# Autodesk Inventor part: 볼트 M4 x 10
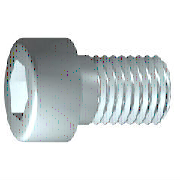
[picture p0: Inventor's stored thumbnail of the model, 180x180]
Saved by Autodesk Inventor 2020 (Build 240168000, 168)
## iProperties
IsCustomPart: 1
Created: 2012-02
Part Number: 볼트 M4 x 10
Material: 스테인리스강
Description: 6각 소켓 머리 캡 나사
Document SubType Name: Modeling
Standard: ISO 4762
Designer: mduedu
Standard Revision: Fourth edition 2004-03-01
Standards Organization: ISO
Language: ko-KR
Size Designation: M4 x 8
Categories: <MemberInstance><Categories><Category DisplayName="조임쇠" InternalName="e4da775c-781d-43d5-af7c-5136215cf5a6" Mnemonic="FSTN"><Category DisplayName="볼트" InternalN
Density: 7.75 g/cm^3
Appearance: 반광택
Author: mduedu
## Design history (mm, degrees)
sketch "스케치1"
  geometry: L1 (-1, 0)-(10, 0); L2 (10, 0)-(10, 2); L3 (10, 2)-(2.1, 2); L4 (2.1, 2)-(1.67, 2); L5 (1.67, 2)-(0, 2); L6 (0, 2)-(0, 3.5); L7 (0, 3.5)-(-4, 3.5); L8 (-4, 3.5)-(-4, 1.732); L9 (-4, 1.732)-(-2, 1.732); L10 (-2, 1.732)-(-1, 0); L11 (-6.8, 0)-(12.8, 0) reference; L12 (0, -0.7)-(0, 4.2) reference; L13 (2.1, 2)-(0, 2)
  constraints: 22 end point, 6 parallel, 2 collinear, 2 perpendicular, 1 horizontal, 1 point on line
  dimensions: "d1" = 7.9 distance from line of L3.end L2 (= GEL); "d2" = 0.42952 distance of L4.end L3.end (computed from GAL); "d3" = 4 distance between parallel lines of L8 L6 (= KOH); "d4" = 2 distance of L8.end L9.end (= INTI); "d5" = 60 deg angle of L10 L1; "d6" = 4 diameter of L3 L1 (= GD); "d7" = 4 diameter of L5 L1 (= BDM); "d8" = 3.4641 diameter of L9 L1 (= 1.1547 x SW); "d9" = 7 diameter of L7 L1 (= KOD); "d26" = 10 distance between parallel lines of L12 L2 (= NLG)
revolve "본체" sketch "스케치1" stored, may be unused: angle "d10" = 90 deg
sketch "스케치2"
  geometry: L1 (0, -4.9)-(0, 4.9) reference; L2 (-4.9, 0)-(4.9, 0) reference; L3 (1.732, 0)-(0.866, -1.5); L4 (0.866, -1.5)-(-0.866, -1.5); L5 (-0.866, -1.5)-(-1.732, 0); L6 (-1.732, 0)-(-0.866, 1.5); L7 (-0.866, 1.5)-(0.866, 1.5); L8 (0.866, 1.5)-(1.732, 0); 2 further points
  constraints: 12 end point, 1 coincident, 1 horizontal alignment, 1 point on line, 12 other
extrude "슬롯" join sketch "스케치2" stored distance "d11" = 10; taper "d12" = 0 deg
workplane "Work Plane1"
fillet "Fillet2" dims "d30" = 0.1 (= R)
body "Solid1"
fillet "모깎기1" dims "d17" = 0.4 (= RR)
feature "스레드" dims "d13" = 7.9 (= GEL), "d14" = 0
chamfer "모따기1" distance "d15" = 0.42941 (= -0.5 x SPD + 0.5 x GD); stored, may be unused: second distance "d16" = 0.42941 (= GUL), angle "d27" = 45 deg
other parameters: "GD" = 4 [user parameter; used in 2 equation terms], "NLG" = 10 [user parameter; used in 1 equation term], "GEL" = 7.9 [user parameter; used in 2 equation terms], "KOD" = 7 [user parameter; used in 1 equation term], "KOH" = 4 [user parameter; used in 1 equation term], "INTI" = 2 [user parameter; used in 1 equation term], "GAL" = 0.42941 (= 0.61345 x PTC) [user parameter; used in 1 equation term], "GUL" = 0.42941 (= 0.61345 x PTC) [user parameter; used in 1 equation term], "BDM" = 4 (= NND) [user parameter; used in 1 equation term], "SW" = 3 [user parameter; used in 2 equation terms], "RR" = 0.4 [user parameter; used in 1 equation term], "SPD" = 3.14117 (= NND - 1.2269 x PTC) [user parameter; used in 1 equation term], "d19" = 0, "d28" = 0, "d29" = 0, "R" = 0.1 [user parameter; used in 1 equation term], "TOA" = 30 deg [user parameter], "GD1" = 3.14117 (= THREADDIA - 1.2269 x PTC) [user parameter], "THREADDIA" = 4 [user parameter; used in 1 equation term], "FAWI" = 45 deg [user parameter], "TPU" = 14.28571 (computed from PTC) [user parameter], "PTC" = 0.7 [user parameter; used in 5 equation terms], "NND" = 4 [user parameter; used in 2 equation terms], "E0" = 3.465 (= 1.155 x SW) [user parameter]
